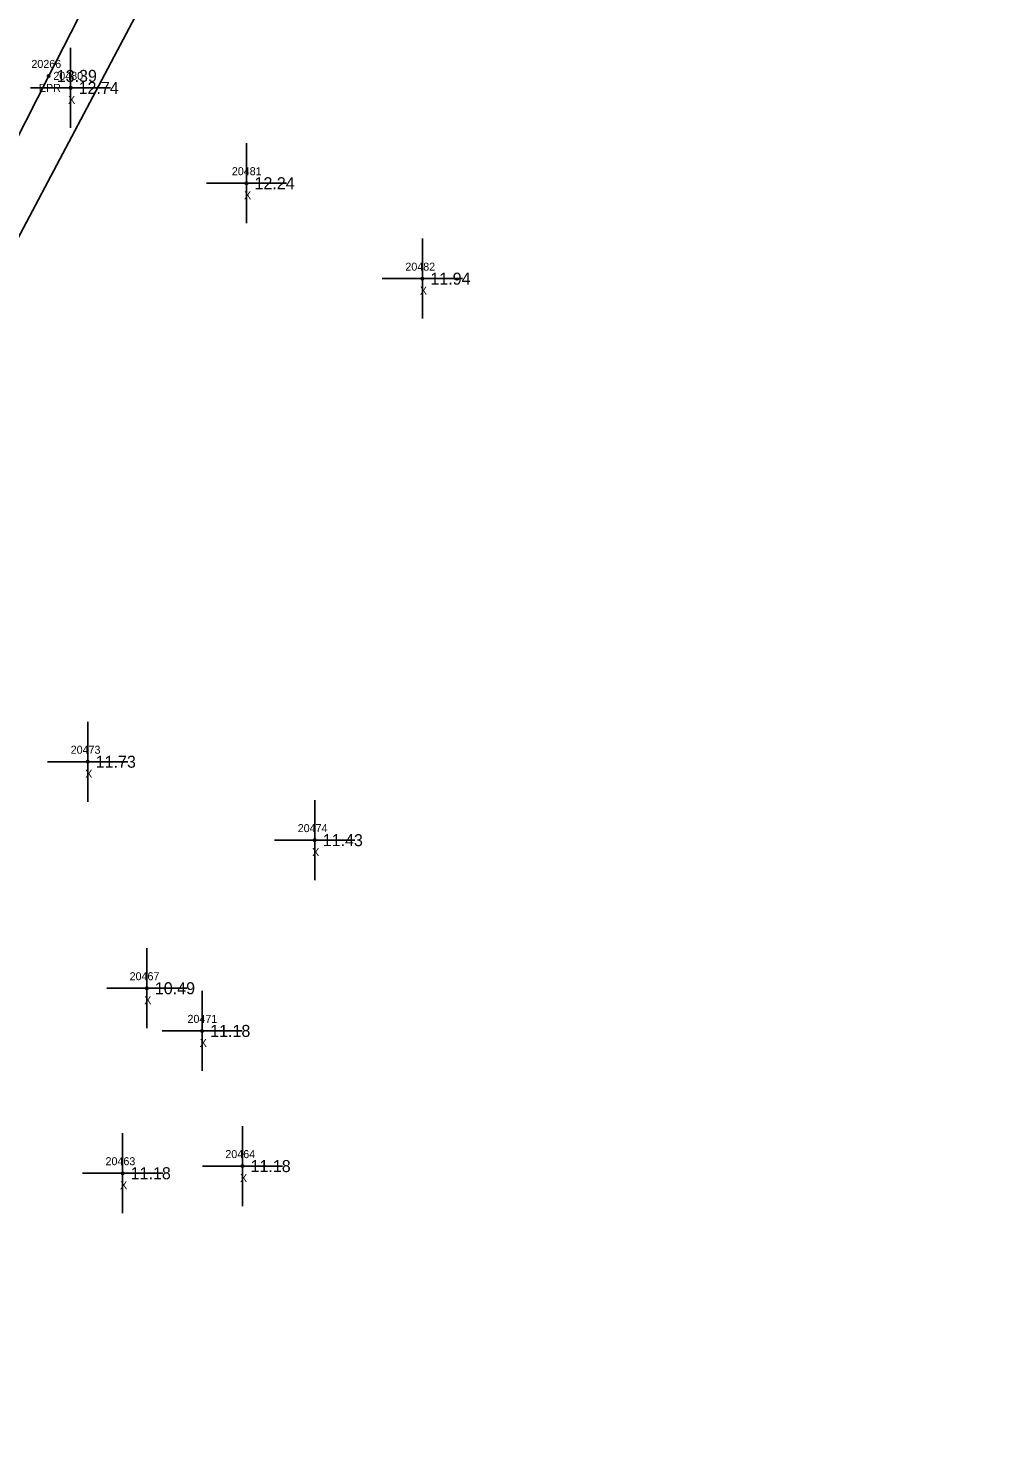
# Model space of a CAD drawing. Extents: x 2072302 to 2072980, y 127650 to 129736.
# Drawn here: x 2072838.2 to 2072957.4, y 128354.3 to 128531.6 of the extents above; entities that cross this region are included whole.
import ezdxf

# ---------------------------------------------------------------- set-up
doc = ezdxf.new("R2010")
doc.units = 0
for name, color, linetype in [('RD_DTM_BkLn1', 7, 'Continuous'), ('RD_EX_Misc', 7, 'Continuous'), ('RD_EX_Misc_txCode', 7, 'Continuous'), ('RD_EX_Road', 7, 'Continuous'), ('RD_EX_Road_txCode', 7, 'Continuous'), ('RD_EX_TX_Misc_ELEV', 7, 'Continuous'), ('RD_EX_TX_Road_ELEV', 7, 'Continuous'), ('RD_SMD_Locator', 7, 'Continuous')]:
    doc.layers.add(name, color=color, linetype=linetype)

msp = doc.modelspace()

# ---------------------------------------------------------------- linework, layer by layer
at = {"layer": 'RD_DTM_BkLn1'}
msp.add_lwpolyline([(2072791.29, 128345.62), (2072800.72, 128429.53), (2072808.9, 128452.58), (2072870.32, 128568.64), (2072876.57, 128573.6), (2072916.77, 128564.68), (2072920.97, 128548.67)], dxfattribs=at)
at = {"layer": 'RD_EX_Misc'}
for p, q in [((2072843.44, 128519.15), (2072843.44, 128529.15)), ((2072838.44, 128524.15), (2072848.44, 128524.15)), ((2072865.41, 128507.23), (2072865.41, 128517.23)), ((2072860.41, 128512.23), (2072870.41, 128512.23)), ((2072887.38, 128495.3), (2072887.38, 128505.3)), ((2072882.38, 128500.3), (2072892.38, 128500.3)), ((2072845.57, 128434.92), (2072845.57, 128444.92)), ((2072840.57, 128439.92), (2072850.57, 128439.92)), ((2072873.93, 128425.12), (2072873.93, 128435.12)), ((2072868.93, 128430.12), (2072878.93, 128430.12)), ((2072852.96, 128406.61), (2072852.96, 128416.61)), ((2072847.96, 128411.61), (2072857.96, 128411.61)), ((2072859.87, 128401.28), (2072859.87, 128411.28)), ((2072854.87, 128406.28), (2072864.87, 128406.28)), ((2072849.94, 128383.49), (2072849.94, 128393.49)), ((2072864.91, 128384.38), (2072864.91, 128394.38)), ((2072844.94, 128388.49), (2072854.94, 128388.49)), ((2072859.91, 128389.38), (2072869.91, 128389.38))]:
    msp.add_line(p, q, dxfattribs=at)
at = {"layer": 'RD_EX_Road'}
msp.add_lwpolyline([(2072789.45, 128345.69), (2072789.46, 128382.93), (2072788.01, 128408.09), (2072794.06, 128431.26), (2072804.3, 128453.88), (2072840.7, 128525.64), (2072876.68, 128596.08), (2072888.72, 128617.36), (2072893.24, 128622.62), (2072899.84, 128627.36), (2072910.72, 128631.76), (2072918.79, 128632.23), (2072935.82, 128627.02), (2072957.37, 128619.98)], dxfattribs=at)
at = {"layer": 'RD_SMD_Locator'}
for centre in [(2072840.7, 128525.64), (2072843.44, 128524.15), (2072865.41, 128512.23), (2072887.38, 128500.3), (2072845.57, 128439.92), (2072873.93, 128430.12), (2072852.96, 128411.61), (2072859.87, 128406.28), (2072849.94, 128388.49), (2072864.91, 128389.38)]:
    msp.add_circle(centre, 0.15, dxfattribs=at)

# ---------------------------------------------------------------- texts
at = {"layer": 'RD_EX_Misc_txCode'}
for s, p in [('20480', (2072841.28, 128525.15)), ('X', (2072843.12, 128522.15)), ('20481', (2072863.58, 128513.23)), ('X', (2072865.1, 128510.23)), ('20482', (2072885.26, 128501.3)), ('X', (2072887.07, 128498.3)), ('20473', (2072843.45, 128440.92)), ('X', (2072845.26, 128437.92)), ('20474', (2072871.81, 128431.12)), ('X', (2072873.61, 128428.12)), ('20467', (2072850.81, 128412.61)), ('X', (2072852.64, 128409.61)), ('20471', (2072858.04, 128407.28)), ('X', (2072859.56, 128404.28)), ('20463', (2072847.8, 128389.49)), ('20464', (2072862.77, 128390.38)), ('X', (2072864.6, 128387.38)), ('X', (2072849.62, 128386.49))]:
    msp.add_text(s, height=1, dxfattribs=at).set_placement(p)
at = {"layer": 'RD_EX_Road_txCode'}
for s, p in [('20266', (2072838.54, 128526.64)), ('EPR', (2072839.47, 128523.64))]:
    msp.add_text(s, height=1, dxfattribs=at).set_placement(p)
at = {"layer": 'RD_EX_TX_Misc_ELEV'}
for s, p in [('12.74', (2072844.44, 128523.4)), ('12.24', (2072866.41, 128511.48)), ('11.94', (2072888.38, 128499.55)), ('11.73', (2072846.57, 128439.17)), ('11.43', (2072874.93, 128429.37)), ('10.49', (2072853.96, 128410.86)), ('11.18', (2072860.87, 128405.53)), ('11.18', (2072865.91, 128388.63)), ('11.18', (2072850.94, 128387.74))]:
    msp.add_text(s, height=1.5, dxfattribs=at).set_placement(p)
at = {"layer": 'RD_EX_TX_Road_ELEV'}
msp.add_text('13.39', height=1.5, dxfattribs=at).set_placement((2072841.7, 128524.89))

doc.saveas('drawing.dxf')
